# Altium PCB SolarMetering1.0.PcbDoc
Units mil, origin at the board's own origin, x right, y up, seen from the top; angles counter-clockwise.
Board outline 6000 x 4000 mil, 2 copper layers (Top Layer, Bottom Layer); 101 components, 74 nets, 331 pads, 0 vias.
Unrouted connection lines stored in the file: 227.
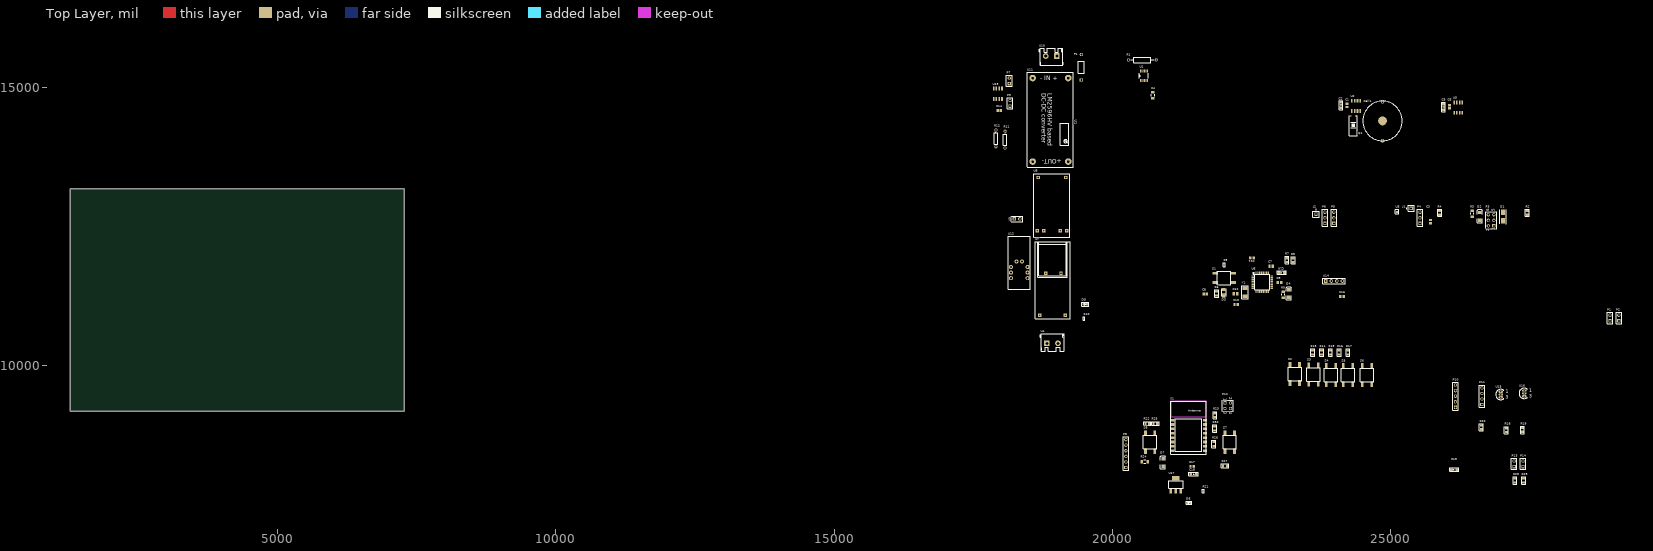
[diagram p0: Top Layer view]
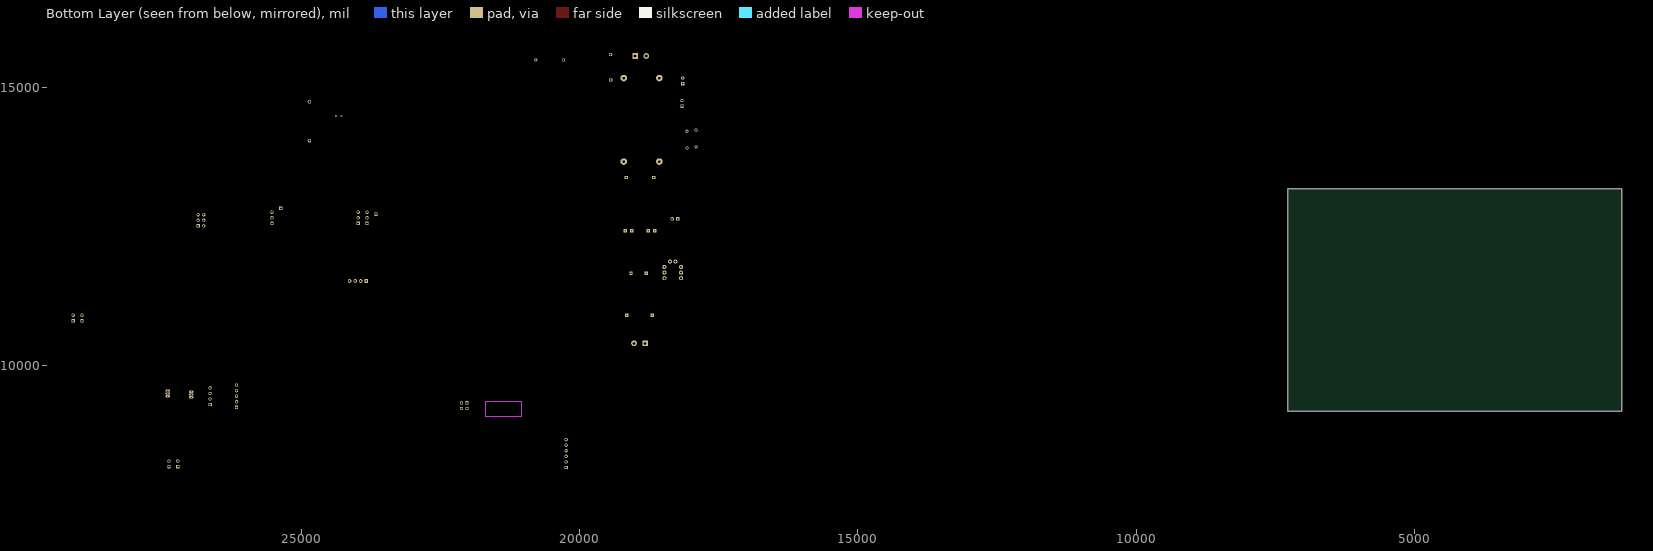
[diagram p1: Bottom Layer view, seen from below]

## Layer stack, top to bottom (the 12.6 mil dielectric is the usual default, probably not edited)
Top Solder: solder mask 0.4, Solder Resist, Dk 3.5
Top Layer: signal copper 1.4
Dielectric 1: dielectric 12.6, FR-4, Dk 4.8
Bottom Layer: signal copper 1.4
Bottom Solder: solder mask 0.4, Solder Resist, Dk 3.5

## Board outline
1280,9185 7280,9185 7280,13185 1280,13185

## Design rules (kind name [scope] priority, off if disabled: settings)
Clearance [All] p1: gap=10
PolygonConnect [All] p1: connectstyle=Relief reliefconductorwidth=10 reliefentries=4 polygonreliefangle="90 Angle" airgapwidth=10
RoutingLayers "Schematic Routing Layers_1" [InNet('XTAL2')] p1: top layer_v5=TRUE bottom layer_v5=FALSE
RoutingLayers "Schematic Routing Layers" [InNet('XTAL1')] p2: top layer_v5=TRUE bottom layer_v5=FALSE
RoutingLayers [All] p3: top layer_v5=TRUE bottom layer_v5=TRUE
RoutingVias [All] p1: holewidth=28 width=50 viastyle="Through Hole" minholewidth=28 minwidth=50 maxholewidth=28 maxwidth=50
SolderMaskExpansion [All] p1: expansion=4
Width "Schematic Width Constraint_3" [InNet('S-IN')] p1: maxlimit=70 minlimit=70 preferedwidth=70 minimp=50.000000 maximp=50.000000 favimp=50.000000
Width "Schematic Width Constraint_2" [InNet('NetP7_1')] p2: maxlimit=70 minlimit=70 preferedwidth=70 minimp=50.000000 maximp=50.000000 favimp=50.000000
Width "Schematic Width Constraint_1" [InNet('NetP9_2')] p3: maxlimit=70 minlimit=70 preferedwidth=70 minimp=50.000000 maximp=50.000000 favimp=50.000000
Width "Schematic Width Constraint" [InNet('DC-DC-IN')] p4: maxlimit=70 minlimit=70 preferedwidth=70 minimp=50.000000 maximp=50.000000 favimp=50.000000
Width [All] p5: maxlimit=10 minlimit=10 preferedwidth=10
29 further rules are at their usual default settings.

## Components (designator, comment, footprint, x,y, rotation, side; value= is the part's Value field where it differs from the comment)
C1 "302010165" C0805 24210,14679.53 r90 top
C2 "302020002" AVX-A 24105,14685 r270 top
C3 "302010165" C0805 25710,12590 r90 top
C4 "302010189" C1206 20725,14860 r90 top
C5 "302020002" AVX-A 25945,14650 r270 top
C6 "302010165" C0805 26050,14655 r90 top
C7 "302010165" C0805 22850,11790 r0 top
C8 "302010165" C0805 21665,11290 r0 top
C9 "302010165" C0805 23000,11500 r0 top
C10 "302020002" AVX-A 23040,11675 r0 top
C11 "302010165" C0805 22505.47,11940 r0 top
C12 "302010018" C0805 22210,11295 r0 top
C13 "302010018" C0805 22220.47,11105 r0 top
C14 "1nF Filter" C0805 17964.53,14590 r0 top
C15 "302020002" AVX-A 26140,8135 r0 top
C16 "302010165" C0805 24120.47,11245 r0 top
C17 "302010165" C0805 21429.53,8190 r0 top
C18 "302020002" AVX-A 21455,8055 r180 top
Cell1 "Cell-CR1616" CellCR1616 24850,14045.67 r90 top
D1 "SMAJ75A-13-F" SMAJ5.0-TVS 27015,12605 r90 top
D2 "LED2" 3.2X1.6X1.1 26595,12685 r90 top
D3 "Diode" "1206 Diode SMD" 22000,11251.89 r90 top
D4 "LED2" 3.2X1.6X1.1 23165,11298.9 r90 top
D5 "304090046" LED-0805 19510,11105 r0 top
D6 "304090045" LED-0603 21375,7540 r0 top
D7 "RED LED   1206" 3.2X1.6X1.1 20905,8263.9 r90 top
F1 "Fuse 2" PIN-W2/E2.8 19440,15365 r90 top
J1 "Socket" PIN1 25365,12830 r90 top
J2 "Socket" PIN1 23655,12725 r0 top
P1 "LTC2945-EN" HDR1X2 28935,10810 r90 top
P2 "LTC2945-OUT-EN" HDR1X2 29095,10810 r90 top
P3 "Header 3X2" HDR2X3 26850,12515 r90 top
P4 "ADR1" HDR1X3 25525,12560 r90 top
P5 "ADR1" HDR1X3 23975,12560 r90 top
P6 "ADR0" HDR1X3 23815,12560 r90 top
P7 "Header 2" HDR1X2 18145,15070 r90 top
P8 "320020077" HDR1X6 20240,8175 r90 top
P9 "Header 2" HDR1X2 18160,14665 r90 top
P10 "MAX6675 Thermocouple Module" HDR1X5 26160,9255 r90 top
P11 "DHT22" HDR1X4 26635,9305 r90 top
P12 "Header 2X2" HDR2X2 22020,9335 r270 top
P13 "Thermistor A" HDR1X2 27215,8190 r90 top
P14 "Thermistor B" HDR1X2 27375,8190 r90 top
Q1 "32.768KHz" RTC-XTAL 24275,14490 r0 top
R1 "Res Semi" AXIAL-0.5 20535,15495 r0 top
R2 "51Ohm" R0805 27450,12750 r0 top
R3 "3.3K" C1206 26460,12735 r90 top
R4 "10K" R0805 25875,12750 r0 top
R5 "301010006" R0402 22005,11815 r0 top
R6 "10K" R0805 21870,11300 r0 top
R7 "4.7K" R0805 23135,11900 r0 top
R8 "4.7K" R0805 23245,11895 r180 top
R9 "301010466" C1206 23065,11280 r270 top
R10 "301010006" R0402 19490,10850 r0 top
R11 "Res1" AXIAL-0.3 18070,14065 r90 top
R12 "Res1" AXIAL-0.3 17905,14085 r270 top
R13 "10K" R0805 23595,10240 r0 top
R14 "10K" R0805 23755,10240 r0 top
R15 "10K" R0805 23915,10240 r0 top
R16 "10K" R0805 24070,10240 r0 top
R17 "10K" R0805 24230,10240 r0 top
R18 "10K" R0805 27075,8845 r0 top
R19 "10K" R0805 27365,8850 r0 top
R20 "10K" R0805 26625,8895 r0 top
R21 "301010006" R0402 21630,7750 r0 top
R22 "10K" R0805 20625,8965 r90 top
R23 "1K" R0805 21840,9115 r0 top
R24 "1K" C1206 20578.15,8280 r180 top
R25 "10K" R0805 20770,8965 r270 top
R26 "10K" R0805 21820,8595 r0 top
R27 "10K" R0805 22020,8205 r90 top
R28 "10K" R0805 27230,7940 r0 top
R29 "10K" R0805 27385,7940 r0 top
R30 "2K" R0805 21835,8875 r180 top
S1 "311020004" SW4-SMD-6.0X6.0X5.0MM 22005,11580 r180 top
S2 "311020004" SW4-SMD-6.0X6.0X5.0MM 23275,9855 r90 top
S3 "311020004" SW4-SMD-6.0X6.0X5.0MM 23610,9845 r90 top
S4 "311020004" SW4-SMD-6.0X6.0X5.0MM 23925,9835 r90 top
S5 "311020004" SW4-SMD-6.0X6.0X5.0MM 24230,9835 r90 top
S6 "311020004" SW4-SMD-6.0X6.0X5.0MM 24570,9835 r90 top
S7 "311020004" SW4-SMD-6.0X6.0X5.0MM 22105,8630 r90 top
S8 "311020004" SW4-SMD-6.0X6.0X5.0MM 20675,8630 r90 top
U1 "LTC2945" LTC2945 20643,15156 r90 top
U2 "DS1307Z+" SO08 24375,14670 r0 top
U3 "ADP119" BGA3x2 25100,12795 r0 top
U4 "Solar OUTPUT PG" "SCREW TERMINAL" 18720.76,10270.19 r0 top
U5 "24LC256" SO08 26210,14640 r0 top
U6 "ATmega328P-AU" TQFP32-0.8-7X7MM 22690,11505 r0 top
U7 "Boost 3.7v To 5V" PowerOut 18608.46,10850.04 r0 top
U8 "TP4056 BAT CHARGER" TP4056 19176.81,12428.31 r180 top
U9 "LI-ION" H2-2.54 18285,12640 r90 top
U10 "Solar Input PG" "SCREW TERMINAL" 19099.24,15699.81 r180 top
U11 "LM2596HV" "LM2596HVS DC-DC step-down module" 19265,13570 r270 top
U12 "MAX17043" MAX17043 18322.17,11870.59 r0 top
U13 "ACS712 30A Current Sensor" SO08 17940,14887.48 r0 top
U14 "OLED128x64" H4-2.54 23980,11525 r90 top
U15 "DS18B20" TO-92 26975,9485 r0 top
U16 "DS18B20" TO-92 27395,9505 r0 top
U17 "AMS1117" AMS1117-3.3 21045,7750 r0 top
X1 "ESP-12" ESP8266-12E 21059.37,8443.46 r0 top
Y1 "306010054" SMT_XTAL 22380,11395.67 r270 top

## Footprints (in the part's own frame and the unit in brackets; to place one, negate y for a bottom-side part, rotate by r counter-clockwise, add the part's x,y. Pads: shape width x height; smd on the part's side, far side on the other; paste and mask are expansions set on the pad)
3.2X1.6X1.1 [mm] "SMT LED; 2 Flat Leads"
  rect 1.5x1.5 smd: 1(-1.75,0) 2(1.75,0)
  silkscreen extent -2.9,-1.15 3.2,1.15
"1206 Diode SMD" [mm] "CD1206-S01575CT-ND"
  rect 1.5x1.6 smd: 1(0,0) 2(3,0)
  silkscreen extent 0,-1 3.5,1
AMS1117-3.3 [mm]
  rect 3.5x2 smd: 0(2.29,5.9)
  rect 1x2 smd: 1(0,0) 2(2.29,0) 3(4.58,0)
  silkscreen extent -1,1.25 5.65,4.8
AVX-A [mil]
  rect 50x50 smd: +(-50,0) -(50,0)
  silkscreen extent -82,-33 82,33
AXIAL-0.3 [mm] "Axial Device, Thru-Hole; 2 Leads; 0.3 in Pin Spacing"
  round 1.4 hole 0.85: 1(-3.81,0) 2(3.81,0)
  silkscreen extent -2.77,-0.76 2.77,0.76
AXIAL-0.5 [mm] "Axial Device, Thru-Hole; 2 Leads; 0.5 in Pin Spacing"
  round 1.4 hole 0.85: 1(-6.35,0) 2(6.35,0)
  silkscreen extent -5.33,-1.27 5.33,1.27
BGA3x2 [mm]
  round 0.295 smd: A1(0,0) A2(0.5,0) B1(0,-0.5) B2(0.5,-0.5) C1(0,-1) C2(0.5,-1)
  silkscreen extent -0.5,-1.5 1,0.5
C0805 [mm] "Chip Capacitor, Body 2.0x1.3mm, IPC High Density"
  rect 1.1x1.4 smd: 1(-0.75,0) 2(0.75,0)
  body extent -1.1,-0.72 1.1,0.72, height 1.4
C1206 [mm] "Chip Capacitor, Body 3.2x1.6mm, IPC High Density"
  rect 1.1x1.7 smd: 1(-1.35,0) 2(1.35,0)
  silkscreen extent -0.4,-0.75 0.4,0.75, body extent -1.7,-0.9 1.7,0.9, height 1.3
CellCR1616 [mm]
  round 1.6 hole 1: 1+(0,0) 2+(17.78,0)
  round 4 smd: 3-(9,0)
  silkscreen extent 0,-9 18,9
ESP8266-12E [mm]
  rect 2x1.2 smd: 1(0.27,14.801) 2(0.27,12.801) 3(0.27,10.801) 4(0.27,8.801) 5(0.27,6.801) 6(0.27,4.801) 7(0.27,2.801) 8(0.27,0.801) 9(15.27,0.801) 10(15.27,2.801) 11(15.27,4.801) 12(15.27,6.801) 13(15.27,8.801) 14(15.27,10.801) 15(15.27,12.801) 16(15.27,14.801)
  Top Layer keep-out region: -0.23,16.301 15.77,16.301 15.77,23.301 -0.23,23.301
  Bottom Layer keep-out region: -0.23,16.301 15.77,16.301 15.77,23.301 -0.23,23.301
  silkscreen extent -0.23,-0.7 15.77,23.3
H2-2.54 [mil]
  rect 65x65 hole 35: 1(0,50)
  round 65 hole 35: 2(0,-50)
  silkscreen extent -50,-100 50,100
H4-2.54 [mil]
  rect 65x65 hole 35: 1(0,150)
  round 65 hole 35: 2(0,50) 3(0,-50) 4(0,-150)
  silkscreen extent -50,-200 50,200
HDR1X2 [mm] "Connector; Header; 2 Position"
  rect 1.5x1.5 hole 0.9: 1(0,0)
  round 1.5 hole 0.9: 2(2.54,0)
  silkscreen extent -1.27,-1.27 3.81,1.27
HDR1X3 [mm] "Connector; Header; 3 Position"
  rect 1.5x1.5 hole 0.9: 1(0,0)
  round 1.5 hole 0.9: 2(2.54,0) 3(5.08,0)
  silkscreen extent -1.27,-1.27 6.35,1.27
HDR1X4 [mm] "Connector; Header; 4 Position"
  rect 1.5x1.5 hole 0.9: 1(0,0)
  round 1.5 hole 0.9: 2(2.54,0) 3(5.08,0) 4(7.62,0)
  silkscreen extent -1.27,-1.27 8.89,1.27
HDR1X5 [mm] "Connector; Header; 5 Position"
  rect 1.5x1.5 hole 0.9: 1(0,0)
  round 1.5 hole 0.9: 2(2.54,0) 3(5.08,0) 4(7.62,0) 5(10.16,0)
  silkscreen extent -1.27,-1.27 11.43,1.27
HDR1X6 [mm] "Connector; Header; 6 Position"
  rect 1.5x1.5 hole 0.9: 1(0,0)
  round 1.5 hole 0.9: 2(2.54,0) 3(5.08,0) 4(7.62,0) 5(10.16,0) 6(12.7,0)
  silkscreen extent -1.27,-1.27 13.97,1.27
HDR2X2 [mm] "Connector; Header; 2x2 Position"
  rect 1.5x1.5 hole 0.9: 1(0,0)
  round 1.5 hole 0.9: 2(0,2.54) 3(2.54,0) 4(2.54,2.54)
  silkscreen extent -1.27,-1.27 3.81,3.81
HDR2X3 [mm] "Connector; Header; 3x2 Position"
  rect 1.5x1.5 hole 0.9: 1(0,0)
  round 1.5 hole 0.9: 2(0,2.54) 3(2.54,0) 4(2.54,2.54) 5(5.08,0) 6(5.08,2.54)
  silkscreen extent -1.27,-1.27 6.35,3.81
LED-0603 [mil]
  rrect25% 30x35 smd: +(-30,0) -(30,0)
  silkscreen extent -52,-25 52,25
LED-0805 [mil]
  rrect25% 35x50 smd: +(-35,0) -(35,0)
  silkscreen extent -62,-35 62,35
"LM2596HVS DC-DC step-down module" [mm]
  round 3 hole 0.914 slot 0.96 at 0 deg: 1(-40.64,-1.524) 2(-40.64,-17.78) 3(-2.54,-17.78) 4(-2.54,-1.524)
  silkscreen extent -43.18,-20.24 0,0.76
LTC2945 [mil] "12MSOP"
  rect 55x17 smd: 1(-31,144) 2(-31,118) 3(-31,93) 4(-31,67) 5(-31,42) 6(-31,16) 7(141,16) 8(141,42) 9(141,67) 10(141,93) 11(141,118) 12(141,144)
  silkscreen extent 7,0 103,160
MAX17043 [mil] "Fuel Guage"
  round 74 hole 40: 1(-47.17,4.41) 2(-147.17,-95.59) 3(-147.17,-195.59) 4(-147.17,-295.59) 5(152.83,-295.59) 6(152.83,-195.59) 7(152.83,-95.59) 8(52.83,4.41)
  silkscreen extent -197,-496 203,454
PIN1 [mm] "Connector; Plug"
  rect 1.5x1.5 hole 0.9: 1(0,0)
  silkscreen extent -1.4,-1.4 1.4,2.17
PIN-W2/E2.8 [mm] "Thru-Hole; 2 Leads"
  rect 1.5x1.5 hole 0.9: 1(-5.825,0)
  round 1.5 hole 0.9: 2(5.825,0)
  silkscreen extent -2.65,-1.4 2.65,1.4
PowerOut [mil] "USB Power Module"
  rect 60x60 hole 30: 1(86.61,57.09) 2(543.31,57.09) 3(190.94,814.96) 4(466.54,814.96)
  silkscreen extent 0,0 630,1378
R0402 [mil]
  rrect50% 19.69x19.69 smd: 1(0,18.21) 2(0,-18.21)
  silkscreen extent -16,-33 16,33
R0805 [mil]
  rrect25% 55x40 smd: 1(0,35) 2(0,-35)
  silkscreen extent -35,-65 35,65
RTC-XTAL [mm] "RTC Crystal 32.768KHz"
  round 0.8 hole 0.5: 1(0,0) 2(2.54,0)
  silkscreen extent -0.5,-9 3,0
"SCREW TERMINAL" [mil] "PG Connector"
  rect 102.4x102.4 hole 55.2: 1(99.24,134.81)
  round 102.4 hole 55.2: 2(299.24,134.81)
  silkscreen extent -15,-3 414,304
SMAJ5.0-TVS [mm] "400W SURFACE MOUNT TRANSIENT VOLTAGE SUPPRESSOR"
  rect 2.5x1.7 smd: 1(0,0) 2(4,0)
  silkscreen extent -1.5,-1.5 5,1.5
SMT_XTAL [mm]
  rect 1.7x2.4 smd: 1(0,0) 2(3.7,0)
  silkscreen extent -1.15,-1.45 4.75,1.45
SO08 [mm]
  rect 0.72x1.78 smd: 1(-1.905,-2.35) 2(-0.635,-2.35) 3(0.635,-2.35) 4(1.905,-2.35) 5(1.905,2.35) 6(0.635,2.35) 7(-0.635,2.35) 8(-1.905,2.35)
SW4-SMD-6.0X6.0X5.0MM [mil]
  rect 100x50 smd: 1(-162.56,85) 2(-162.56,-85) 3(162.56,-85) 4(162.56,85)
  silkscreen extent -120,-120 120,120
TO-92 [mm] "TO, Flat Index; 3 In-Line, Axial Leads; Body Dia. 4.6mm; Leads 0.41 x 0.39 mm (max)"
  oval 2x1 hole 0.7: 1(0,1.27) 2(0,0) 3(0,-1.27)
  silkscreen extent -2.34,-2.34 1.35,2.34
TP4056 [mil] "TP-4056 Module"
  rect 60x60 hole 30: 1(19.69,-956.69) 2(511.81,-956.69) 3(0,0) 4(531.5,0) 5(118.11,0) 6(413.39,0)
  silkscreen extent -59,-1024 591,118
TQFP32-0.8-7X7MM [mil]
  rect 50x22 smd: 1(-169,110.24) 2(-169,78.74) 3(-169,47.24) 4(-169,15.75) 5(-169,-15.75) 6(-169,-47.24) 7(-169,-78.74) 8(-169,-110.24) 17(169,-110.24) 18(169,-78.74) 19(169,-47.24) 20(169,-15.75) 21(169,15.75) 22(169,47.24) 23(169,78.74) 24(169,110.24)
  rect 22x50 smd: 9(-110.24,-169) 10(-78.74,-169) 11(-47.24,-169) 12(-15.75,-169) 13(15.75,-169) 14(47.24,-169) 15(78.74,-169) 16(110.24,-169) 25(110.24,169) 26(78.74,169) 27(47.24,169) 28(15.75,169) 29(-15.75,169) 30(-47.24,169) 31(-78.74,169) 32(-110.24,169)
  silkscreen extent -170,-138 138,170

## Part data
C1 C3 C6 C7 C8 C9 C11 C16 C17: library part CERAMIC-100NF-50V-10%-X7R(0805), "100nF"
C2 C5 C10 C15 C18: library part TANTALUM-SMD-10UF-16V-10%(AVX-A), "10uF Cap Decoupling 16V"
C4: library part CERAMIC-1NF-1KV-10%-X7R?(1206)
C12 C13: library part CERAMIC-22PF-50V-5%-NPO(0402)
C14: library part CERAMIC-100NF-25V-10%-X7R(0402), "1nF Filter Cap as per Datasheet"
D1: library part "D Schottky", "SMA"
D2 D4: "Typical RED, GREEN, YELLOW, AMBER GaAs LED"
D3: "Default Diode"
D5: library part SMD-LED-CLEAR-RED(0805)
D6: library part SMD-LED-CLEAR-BLUE(0603)
D7: library part LED2, "Typical RED, GREEN, YELLOW, AMBER GaAs LED"
F1: "Fuse"
P1 P2 P13 P14: library part "Header 2", "Header, 2-Pin"
P3: "Header, 3-Pin, Dual row"
P4 P5 P6: library part "Header 3", "Header, 3-Pin"
P7 P9: "Header, 2-Pin"
P8: library part DIP-BLACK-MALE-HEADER(2X3P-2.54)-2.54
P10: library part "Header 5", "Header, 5-Pin"
P11: library part "Header 4", "Header, 4-Pin"
P12: "Header, 2-Pin, Dual row"
Q1: library part CRYTALTC38H
R1: "Semiconductor Resistor"
R2 R4 R7 R8 R13 R14 R15 R16 R17 R18 R19 R20 R22 R23 R25 R26 R27 R28 R29 R30: library part RESISTOR0805_NOOUTLINE, "Resistors   For new designs, use the packages preceded by an '_' character since they are more reliable:   The following footprints should be used on most boards: _0402 - Standard footprint for regular board layouts  _0603 - Standard footprint for regular board layouts  _0805 - Standard footprint for regular board layouts  _1206 - Standard footprint for regular board layouts       For extremely tight-pitch boards where space is at a premium, the following 'micro-pitch' footprints can be used (smaller pads, no silkscreen outline, etc.): _0402MP - Micro-pitch footprint for very dense/compact boards  _0603MP - Micro-pitch footprint for very dense/compact boards  _0805MP - Micro-pitch footprint for very dense/compact boards  _1206MP - Micro-pitch footprint for very dense/compact boards"
R3 R9: library part SMD-RES-330R-1%-1/16W(0402)
R5 R6 R10 R21: library part SMD-RES-1K-5%-1/16W(0402)
R11 R12: "Resistor"
R24: library part SMD-RES-330R-1%-1/16W(0402), "1K 1206"
S1 S2 S3 S4 S5 S6 S7 S8: library part SMD-SWITCH-TACTILE-SPST-NO(4P-D6.0MM)
U1: "V I P Monitor I2C Interface"
U2: "RTC circuit%3B I2C%3B NV SRAM%3B 56B%3B 4.5%C3%B75.5VDC%3B SO8"
U4 U10: library part PG_IN
U6: "8-bit AVR Microcontroller, 32KB Flash, 1KB EEPROM, 2KB SRAM, 32-pin TQFP, Industrial Grade (-40°C to 85°C)"
U7: library part "PowerOut Module", "USB Power Out module"
U8: library part TP4056, "TP4056 Module"
U9: library part Battery, "Li Ion Battery 3.7V"
U11: "DC DC Adjustable Buck converter input upto 60V"
U12: "Battery Fuel Guage"
U13: library part ACS712
U14: library part DIP-BLACK-MALE-HEADER-VERT(4P-2.54)
U15 U16: "On Board Temperature Sensor"
U17: "3.3V Regulator"
Y1: library part SMD-CRYSTAL-16MHZ-8PF-20PPM-40R(2P-5.0X3.2MM)

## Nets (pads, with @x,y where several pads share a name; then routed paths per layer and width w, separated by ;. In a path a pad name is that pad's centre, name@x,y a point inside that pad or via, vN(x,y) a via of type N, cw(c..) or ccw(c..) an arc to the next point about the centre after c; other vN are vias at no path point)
_SCL: U12.6
_SDA: U12.7
ACS-OUT: U6.19 U13.7
ADIN: J2.1 U1.5
ALERT-LTC2945: D2.2 R4.1 U1.10 U6.32
BAT-ALT: U6.1 U12.4
BAT-OUT+: U7.2 U8.3
BAT-OUT-: U7.1 U8.4
BATT+: U12.2
BATT-CHG+: U8.5 U9.1 U12.8
BATT-CHG-: U8.6 U9.2 U12.1
CH-PD: R25.1 X1.3
CS-TC: P10.4
DC-DC-IN: P2.2 P9.1 U4.1 U11.1
DHT-DATA: P11.2 R20.1 U6.10
DOWN: R15.1 S4.4 U6.14
DS1820-DATA-1: R18.2 U6.2 U15.2
DS1820-DATA-2: R19.2 U6.9 U16.2
ESP-RXD: P12.4 U6.31
ESP-RXD-PIN: R23.1 R30.2 X1.15
ESP-TXD: P12.2 U6.30
GND: C1.1 C2.- C3.1 C4.1 C5.- C6.1 C7.1 C8.2 C9.1 C10.- C11.1 C12.1 C13.1 C14.1 C15.- C16.1 C17.1 C18.- Cell1.3- D1.1 D4.2 D5.- D6.- P5.3 P6.1 P8.4 P10.1 P11.4 P13.1 P14.1 R5.1 R12.1 R27.1 R30.1 S1.1 S1.4 S2.2 S3.2 S4.2 S5.2 S6.2 S7.2 S8.2 U1.6 U2.4 U3.C2 U4.2 U5.1 U5.2 U5.3 U5.4 U6.3 U6.5 U6.21 U7.3 U10.2 U11.2 U12.3 U13.5 U14.2 U15.1 U16.1 U17.1 X1.9
GPIO0: D7.2 S7.4 X1.12
GPIO2: R26.1 X1.11
GPIO15: R27.2 X1.10
LEFT: R16.1 S5.4 U6.13
MISO: P8.1
MOSI: P8.5
NetC3_2: C3.2 P3.2 P3.4 P3.6 U1.1
NetC4_2: C4.2 P3.1 R2.2
NetC9_2: C9.2 U6.20
NetC14_2: C14.2 U13.6
NetCell1_1+: Cell1.1+ Cell1.2+ U2.3
NetD1_2: D1.2 P1.2 R1.1 R2.1 U1.12
NetD2_1: D2.1 R3.2
NetD4_1: D4.1 R9.2
NetD5_+: D5.+ R10.2
NetD6_+: D6.+ R21.2
NetD7_1: D7.1 R24.2
NetF1_2: F1.2 U10.1
NetJ1_1: J1.1 P3.5
NetP2_1: P2.1 R1.2 U1.11
NetP4_3: P4.3 U1.9
NetP5_2: P5.2 U1.3
NetP6_2: P6.2 U1.4
NetP7_1: P7.1 U13.1 U13.2
NetP9_2: P9.2 U13.3 U13.4
NetP12_1: P12.1 X1.16
NetP12_3: P12.3 R23.2
NetQ1_1: Q1.1 U2.1
NetQ1_2: Q1.2 U2.2
PWR5+: U8.1 U11.4
PWR5-: U8.2 U11.3
RESET: C8.1 D3.1 P8.3 R5.2 R6.1 S1.2 S1.3 U6.29
RESET_ESP: R22.1 S8.4 X1.1
RIGHT: R13.1 S2.4 U6.16
S-IN: F1.1 P1.1 P7.2
S_IN: R11.2
SCK: P8.2 R9.1 U6.17
SCL: P10.5 R8.1 U1.7 U2.6 U5.6 U6.28 U14.3
SDA: P4.2 P10.3 R7.1 U1.8 U2.5 U5.5 U6.27 U14.4
SELECT: R17.1 S6.4 U6.12
THERMISTOR-A: P13.2 R28.2 U6.23
THERMISTOR-B: P14.2 R29.2 U6.24
UP: R14.1 S3.4 U6.15
VCC-3V3: C17.2 C18.+ R13.2 R14.2 R15.2 R16.2 R17.2 R22.2 R24.1 R25.2 R26.2 U17.2 X1.8
VCC-5V: C1.2 C2.+ C5.+ C6.2 C7.2 C10.+ C11.2 C15.+ C16.2 P3.3 P5.1 P6.3 P8.6 R3.1 R4.2 R7.2 R8.2 U1.2 U3.A1 U3.B1 U6.4 U6.6 U6.18 U7.4 U13.8
VCC-5V-EN: D3.2 P10.2 P11.1 R6.2 R18.1 R19.1 R20.2 R28.1 R29.1 U2.8 U3.A2 U3.B2 U5.8 U14.1 U15.3 U16.3 U17.3
VCC_3.3V: R21.1
VCC_5V: R10.1
VDVR_IN: R11.1 R12.2
WAKE-UP: U3.C1 U6.26
XTAL1: C12.2 U6.7 Y1.1
XTAL2: C13.2 U6.8 Y1.2
pads on no net: P4.1 P11.3 S2.1 S2.3 S3.1 S3.3 S4.1 S4.3 S5.1 S5.3 S6.1 S6.3 S7.1 S7.3 S8.1 S8.3 U2.7 U5.7 U6.11 U6.22 U6.25 U12.5 U17.0 X1.2 X1.4 X1.5 X1.6 X1.7 X1.13 X1.14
